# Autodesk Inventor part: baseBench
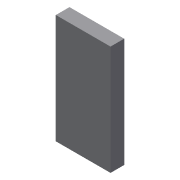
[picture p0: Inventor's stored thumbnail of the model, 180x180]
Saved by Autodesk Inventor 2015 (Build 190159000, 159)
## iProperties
Created: 2016-08
Part Number: baseBench
Material: EIFS, Exterior Insulation
Document SubType Name: Modeling
Designer: user
Density: 0.023 g/cm^3
Appearance: Gray
Author: user
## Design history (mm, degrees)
sketch "Sketch1"
  geometry: L1 (0, 25.4)-(25.4, 25.4); L2 (25.4, 25.4)-(25.4, -25.4); L3 (25.4, -25.4)-(0, -25.4); L4 (0, -25.4)-(0, 25.4); 1 further point
  constraints: 8 end point, 2 parallel, 1 horizontal, 1 perpendicular
  dimensions: "d0" = 25.4 distance of L2.end L3.end; "d1" = 50.8 distance of L1.end L2.end
extrude "Extrusion1" new body sketch "Sketch1" distance "d2" = 6.35; taper "d3" = 0 deg
workplane "Work Plane1"
sketch "Sketch2"
  geometry: L1 (7.943, 26.127)-(-1.582, 26.127); L2 (-1.582, 26.127)-(-1.582, -24.673); L3 (-1.582, -24.673)-(7.943, -24.673); L4 (7.943, -24.673)-(7.943, 26.127); 1 further point
  constraints: 8 end point, 2 parallel, 1 horizontal, 1 perpendicular
  dimensions: "d4" = 9.525 distance of L3.end L2.end; "d5" = 50.8 distance of L2.end L1.end
extrude "Extrusion2" join sketch "Sketch2" distance "d6" = 6.35; taper "d7" = 0 deg
body "Solid1"
